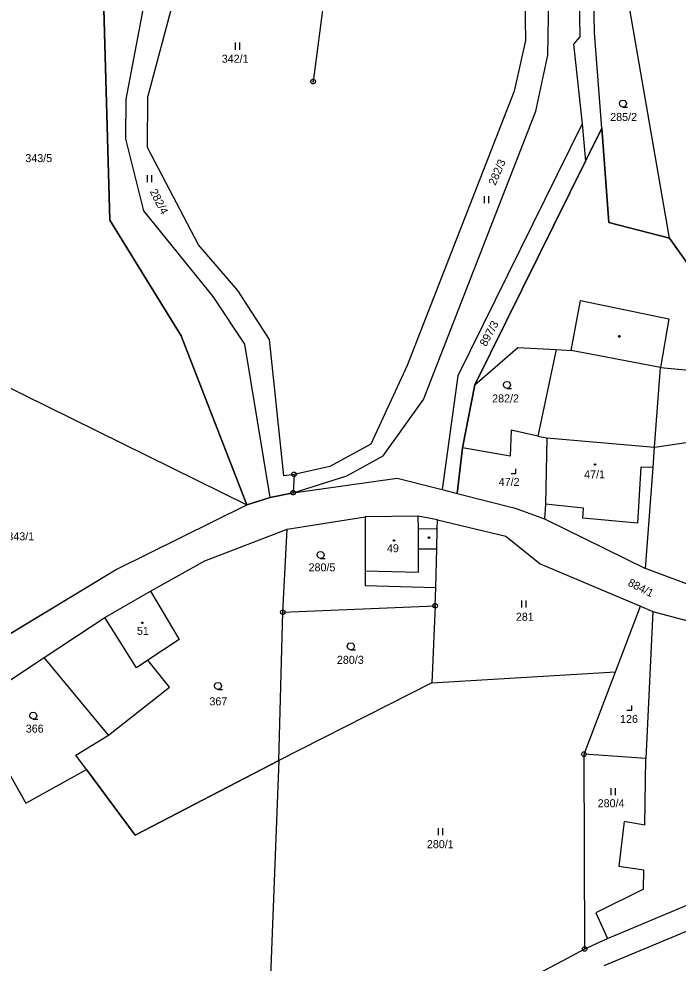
# Model space of a CAD drawing. Extents: x -580551 to -575069, y -1073031 to -1067931.
# Drawn here: x -577343.9 to -577203.9, y -1069968.7 to -1069768.1 of the extents above; entities that cross this region are included whole.
import ezdxf

# ---------------------------------------------------------------- set-up
doc = ezdxf.new("R2010")
doc.units = 0
for name, color, linetype in [('Druh pozemku', 7, 'Continuous'), ('Geodetické body', 7, 'Continuous'), ('Hranice z DKM', 7, 'Continuous'), ('Parcela', 7, 'Continuous'), ('Parcelní číslo', 7, 'Continuous'), ('Parcelní číslo_stavba', 7, 'Continuous'), ('SR - hranice státu', 7, 'Continuous'), ('Vnitřní kresba', 7, 'Continuous'), ('Vrstva 6', 7, 'Continuous')]:
    doc.layers.add(name, color=color, linetype=linetype)

msp = doc.modelspace()

# ---------------------------------------------------------------- linework, layer by layer
at = {"layer": 'Druh pozemku'}
for p, q in [((-577297.96, -1069773.18), (-577297.96, -1069774.68)), ((-577296.96, -1069774.68), (-577296.96, -1069773.18)), ((-577316.64, -1069801.35), (-577316.64, -1069802.85)), ((-577315.64, -1069802.85), (-577315.64, -1069801.35)), ((-577245.06, -1069805.78), (-577245.06, -1069807.28)), ((-577244.06, -1069807.28), (-577244.06, -1069805.78)), ((-577237.12, -1069891.66), (-577237.12, -1069893.16)), ((-577236.12, -1069893.16), (-577236.12, -1069891.66)), ((-577218.17, -1069931.53), (-577218.17, -1069933.03)), ((-577217.17, -1069933.03), (-577217.17, -1069931.53)), ((-577254.83, -1069940.05), (-577254.83, -1069941.55)), ((-577253.83, -1069941.55), (-577253.83, -1069940.05))]:
    msp.add_line(p, q, dxfattribs=at)
for points in [[(-577215.58, -1069786.86), (-577215.96, -1069786.76), (-577216.23, -1069786.49), (-577216.33, -1069786.12), (-577216.23, -1069785.75), (-577215.96, -1069785.48), (-577215.59, -1069785.38), (-577215.22, -1069785.48), (-577214.95, -1069785.75), (-577214.85, -1069786.13), (-577214.95, -1069786.51), (-577215.22, -1069786.78), (-577215.6, -1069786.88), (-577214.6, -1069786.88)], [(-577240.21, -1069846.62), (-577240.59, -1069846.52), (-577240.86, -1069846.25), (-577240.96, -1069845.88), (-577240.86, -1069845.51), (-577240.59, -1069845.24), (-577240.22, -1069845.14), (-577239.85, -1069845.24), (-577239.58, -1069845.51), (-577239.48, -1069845.89), (-577239.58, -1069846.27), (-577239.85, -1069846.54), (-577240.23, -1069846.64), (-577239.23, -1069846.64)], [(-577239.34, -1069864.71), (-577238.34, -1069864.71), (-577238.34, -1069863.71)], [(-577279.8, -1069882.74), (-577280.18, -1069882.64), (-577280.45, -1069882.37), (-577280.55, -1069882), (-577280.45, -1069881.63), (-577280.18, -1069881.36), (-577279.81, -1069881.26), (-577279.44, -1069881.36), (-577279.17, -1069881.63), (-577279.07, -1069882.01), (-577279.17, -1069882.39), (-577279.44, -1069882.66), (-577279.82, -1069882.76), (-577278.82, -1069882.76)], [(-577273.39, -1069902.15), (-577273.77, -1069902.05), (-577274.04, -1069901.78), (-577274.14, -1069901.41), (-577274.04, -1069901.04), (-577273.77, -1069900.77), (-577273.4, -1069900.67), (-577273.03, -1069900.77), (-577272.76, -1069901.04), (-577272.66, -1069901.42), (-577272.76, -1069901.8), (-577273.03, -1069902.07), (-577273.41, -1069902.17), (-577272.41, -1069902.17)], [(-577301.58, -1069910.56), (-577301.96, -1069910.46), (-577302.23, -1069910.19), (-577302.33, -1069909.82), (-577302.23, -1069909.45), (-577301.96, -1069909.18), (-577301.59, -1069909.08), (-577301.22, -1069909.18), (-577300.95, -1069909.45), (-577300.85, -1069909.83), (-577300.95, -1069910.21), (-577301.22, -1069910.48), (-577301.6, -1069910.58), (-577300.6, -1069910.58)], [(-577340.82, -1069916.88), (-577341.2, -1069916.78), (-577341.47, -1069916.51), (-577341.57, -1069916.14), (-577341.47, -1069915.77), (-577341.2, -1069915.5), (-577340.83, -1069915.4), (-577340.46, -1069915.5), (-577340.19, -1069915.77), (-577340.09, -1069916.15), (-577340.19, -1069916.53), (-577340.46, -1069916.8), (-577340.84, -1069916.9), (-577339.84, -1069916.9)], [(-577214.73, -1069914.99), (-577213.73, -1069914.99), (-577213.73, -1069913.99)]]:
    msp.add_lwpolyline(points, dxfattribs=at)
for points in [[(-577216.26, -1069835.42), (-577216.17, -1069835.57), (-577216.26, -1069835.72), (-577216.44, -1069835.72), (-577216.53, -1069835.57), (-577216.44, -1069835.42)], [(-577221.45, -1069862.62), (-577221.36, -1069862.77), (-577221.45, -1069862.92), (-577221.63, -1069862.92), (-577221.72, -1069862.77), (-577221.63, -1069862.62)], [(-577264.11, -1069878.8), (-577264.02, -1069878.95), (-577264.11, -1069879.1), (-577264.29, -1069879.1), (-577264.38, -1069878.95), (-577264.29, -1069878.8)], [(-577256.67, -1069878.19), (-577256.58, -1069878.34), (-577256.67, -1069878.49), (-577256.85, -1069878.49), (-577256.94, -1069878.34), (-577256.85, -1069878.19)], [(-577317.56, -1069896.28), (-577317.47, -1069896.43), (-577317.56, -1069896.58), (-577317.74, -1069896.58), (-577317.83, -1069896.43), (-577317.74, -1069896.28)]]:
    msp.add_lwpolyline(points, close=True, dxfattribs=at)
at = {"layer": 'Geodetické body'}
for p, q in [((-577281.5, -1069781.45), (-577281.26, -1069781.45)), ((-577285.55, -1069864.9), (-577285.31, -1069864.9)), ((-577285.74, -1069868.8), (-577285.5, -1069868.8)), ((-577255.59, -1069892.81), (-577255.35, -1069892.81)), ((-577287.92, -1069894.19), (-577287.68, -1069894.19)), ((-577223.97, -1069924.33), (-577223.73, -1069924.33)), ((-577223.83, -1069965.71), (-577223.59, -1069965.71))]:
    msp.add_line(p, q, dxfattribs=at)
for points in [[(-577281.23, -1069780.97), (-577280.98, -1069781.15), (-577280.88, -1069781.44), (-577280.98, -1069781.73), (-577281.23, -1069781.91), (-577281.54, -1069781.91), (-577281.79, -1069781.73), (-577281.89, -1069781.44), (-577281.79, -1069781.15), (-577281.54, -1069780.97)], [(-577285.28, -1069864.42), (-577285.03, -1069864.6), (-577284.93, -1069864.89), (-577285.03, -1069865.18), (-577285.28, -1069865.36), (-577285.59, -1069865.36), (-577285.84, -1069865.18), (-577285.94, -1069864.89), (-577285.84, -1069864.6), (-577285.59, -1069864.42)], [(-577285.47, -1069868.32), (-577285.22, -1069868.5), (-577285.12, -1069868.79), (-577285.22, -1069869.08), (-577285.47, -1069869.26), (-577285.78, -1069869.26), (-577286.03, -1069869.08), (-577286.13, -1069868.79), (-577286.03, -1069868.5), (-577285.78, -1069868.32)], [(-577287.65, -1069893.71), (-577287.4, -1069893.89), (-577287.3, -1069894.18), (-577287.4, -1069894.47), (-577287.65, -1069894.65), (-577287.96, -1069894.65), (-577288.21, -1069894.47), (-577288.31, -1069894.18), (-577288.21, -1069893.89), (-577287.96, -1069893.71)], [(-577255.32, -1069892.33), (-577255.07, -1069892.51), (-577254.97, -1069892.8), (-577255.07, -1069893.09), (-577255.32, -1069893.27), (-577255.63, -1069893.27), (-577255.88, -1069893.09), (-577255.98, -1069892.8), (-577255.88, -1069892.51), (-577255.63, -1069892.33)], [(-577223.7, -1069923.85), (-577223.45, -1069924.03), (-577223.35, -1069924.32), (-577223.45, -1069924.61), (-577223.7, -1069924.79), (-577224.01, -1069924.79), (-577224.26, -1069924.61), (-577224.36, -1069924.32), (-577224.26, -1069924.03), (-577224.01, -1069923.85)], [(-577223.56, -1069965.23), (-577223.31, -1069965.41), (-577223.21, -1069965.7), (-577223.31, -1069965.99), (-577223.56, -1069966.17), (-577223.87, -1069966.17), (-577224.12, -1069965.99), (-577224.22, -1069965.7), (-577224.12, -1069965.41), (-577223.87, -1069965.23)]]:
    msp.add_lwpolyline(points, close=True, dxfattribs=at)
at = {"layer": 'Hranice z DKM'}
msp.add_lwpolyline([(-577324.89, -1069726.66), (-577326.18, -1069753.47), (-577324.56, -1069810.92), (-577309.38, -1069835.47), (-577295.46, -1069871.36)], dxfattribs=at)
at = {"layer": 'Parcela'}
for p, q in [((-577225.74, -1069711.96), (-577224.72, -1069771.95)), ((-577205.71, -1069814.7), (-577223.18, -1069713.24)), ((-577221.6, -1069771.08), (-577223.18, -1069713.24)), ((-577300.14, -1069723.1), (-577316.47, -1069784.57)), ((-577231.53, -1069775.83), (-577230.82, -1069724.31)), ((-577236.87, -1069727.44), (-577236.28, -1069772.73)), ((-577276.54, -1069744.84), (-577281.38, -1069781.45)), ((-577324.56, -1069810.92), (-577326.18, -1069753.47)), ((-577321.11, -1069785.16), (-577315.7, -1069757.11)), ((-577220.08, -1069791.36), (-577221.6, -1069771.08)), ((-577236.28, -1069772.73), (-577238.72, -1069783.5)), ((-577224.72, -1069771.95), (-577226.09, -1069773.52)), ((-577226.09, -1069773.52), (-577224.26, -1069790.42)), ((-577234.1, -1069787.75), (-577231.53, -1069775.83)), ((-577238.72, -1069783.5), (-577261.41, -1069841.79)), ((-577321.13, -1069793.6), (-577321.11, -1069785.16)), ((-577316.53, -1069795.46), (-577316.47, -1069784.57)), ((-577257.96, -1069848.97), (-577234.1, -1069787.75)), ((-577224.26, -1069790.42), (-577250.62, -1069843.96)), ((-577220.08, -1069791.36), (-577223.56, -1069798.39)), ((-577218.58, -1069811.4), (-577220.08, -1069791.36)), ((-577317.34, -1069808.9), (-577321.13, -1069793.6)), ((-577305.72, -1069816.14), (-577316.53, -1069795.46)), ((-577223.56, -1069798.39), (-577247.03, -1069845.89)), ((-577302.59, -1069827.11), (-577317.34, -1069808.9)), ((-577309.38, -1069835.47), (-577324.56, -1069810.92)), ((-577205.71, -1069814.7), (-577218.58, -1069811.4)), ((-577185.48, -1069843.33), (-577205.71, -1069814.7)), ((-577297.37, -1069825.86), (-577305.72, -1069816.14)), ((-577295.86, -1069837.2), (-577302.59, -1069827.11)), ((-577290.64, -1069836.25), (-577297.37, -1069825.86)), ((-577295.46, -1069871.36), (-577309.38, -1069835.47)), ((-577290.48, -1069869.82), (-577295.86, -1069837.2)), ((-577287.63, -1069865.19), (-577290.64, -1069836.25)), ((-577247.03, -1069845.89), (-577237.93, -1069837.93)), ((-577237.93, -1069837.93), (-577229.77, -1069838.35)), ((-577229.77, -1069838.35), (-577233.66, -1069856.79)), ((-577353.77, -1069842.63), (-577295.46, -1069871.36)), ((-577261.41, -1069841.79), (-577269.12, -1069858.46)), ((-577208.88, -1069859.13), (-577207.6, -1069842.17)), ((-577207.6, -1069842.17), (-577188.34, -1069843.99)), ((-577250.62, -1069843.96), (-577253.98, -1069868.14)), ((-577247.03, -1069845.89), (-577249.65, -1069859.24)), ((-577266.5, -1069860.95), (-577257.96, -1069848.97)), ((-577239.34, -1069855.53), (-577239.55, -1069861.06)), ((-577233.66, -1069856.79), (-577239.34, -1069855.53)), ((-577233.66, -1069856.79), (-577231.72, -1069857.16)), ((-577231.72, -1069857.16), (-577232.07, -1069871.21)), ((-577208.88, -1069859.13), (-577191.14, -1069856.54)), ((-577269.12, -1069858.46), (-577277.83, -1069863.22)), ((-577249.65, -1069859.24), (-577250.76, -1069868.95)), ((-577239.55, -1069861.06), (-577249.65, -1069859.24)), ((-577209.2, -1069863.44), (-577208.88, -1069859.13)), ((-577274.25, -1069865.2), (-577266.5, -1069860.95)), ((-577277.83, -1069863.22), (-577285.43, -1069864.9)), ((-577210.81, -1069884.91), (-577209.2, -1069863.44)), ((-577285.43, -1069864.9), (-577287.63, -1069865.19)), ((-577285.43, -1069864.9), (-577285.62, -1069868.8)), ((-577285.62, -1069868.8), (-577274.25, -1069865.2)), ((-577285.62, -1069868.8), (-577263.51, -1069865.73)), ((-577263.51, -1069865.73), (-577253.98, -1069868.14)), ((-577290.48, -1069869.82), (-577295.46, -1069871.36)), ((-577285.62, -1069868.8), (-577290.48, -1069869.82)), ((-577253.98, -1069868.14), (-577250.76, -1069868.95)), ((-577250.76, -1069868.95), (-577238.45, -1069872.07)), ((-577323.38, -1069885.15), (-577295.46, -1069871.36)), ((-577232.07, -1069871.21), (-577232.25, -1069874.31)), ((-577259.07, -1069873.76), (-577270.35, -1069873.92)), ((-577254.98, -1069874.53), (-577259.07, -1069873.76)), ((-577238.45, -1069872.07), (-577232.25, -1069874.31)), ((-577286.87, -1069876.53), (-577270.35, -1069873.92)), ((-577270.35, -1069873.92), (-577270.34, -1069885.39)), ((-577255.06, -1069876.54), (-577254.98, -1069874.53)), ((-577254.98, -1069874.53), (-577240.49, -1069878.01)), ((-577232.25, -1069874.31), (-577210.81, -1069884.91)), ((-577304.4, -1069883.25), (-577286.87, -1069876.53)), ((-577287.8, -1069894.19), (-577286.87, -1069876.53)), ((-577255.14, -1069880.74), (-577255.06, -1069876.54)), ((-577240.49, -1069878.01), (-577233.14, -1069883.91)), ((-577255.3, -1069888.94), (-577255.14, -1069880.74)), ((-577315.89, -1069889.69), (-577304.4, -1069883.25)), ((-577364.42, -1069909.96), (-577323.38, -1069885.15)), ((-577270.34, -1069885.39), (-577270.34, -1069888.48)), ((-577233.14, -1069883.91), (-577211.86, -1069892.91)), ((-577195.72, -1069890.5), (-577210.81, -1069884.91)), ((-577325.63, -1069895.3), (-577315.89, -1069889.69)), ((-577315.89, -1069889.69), (-577309.81, -1069899.98)), ((-577270.34, -1069888.48), (-577255.3, -1069888.94)), ((-577255.47, -1069892.81), (-577255.3, -1069888.94)), ((-577287.8, -1069894.19), (-577255.47, -1069892.81)), ((-577255.47, -1069892.81), (-577256.18, -1069909.15)), ((-577217.17, -1069906.82), (-577211.86, -1069892.91)), ((-577211.86, -1069892.91), (-577209.21, -1069894.03)), ((-577338.5, -1069903.82), (-577325.63, -1069895.3)), ((-577288.66, -1069925.7), (-577287.8, -1069894.19)), ((-577209.21, -1069894.03), (-577210.7, -1069925.24)), ((-577209.21, -1069894.03), (-577201.02, -1069896.19)), ((-577309.81, -1069899.98), (-577316.47, -1069904.38)), ((-577354.01, -1069914.08), (-577338.5, -1069903.82)), ((-577324.82, -1069920.26), (-577338.5, -1069903.82)), ((-577311.9, -1069910.08), (-577316.47, -1069904.38)), ((-577256.18, -1069909.15), (-577217.17, -1069906.82)), ((-577223.85, -1069924.33), (-577217.17, -1069906.82)), ((-577256.18, -1069909.15), (-577288.66, -1069925.7)), ((-577324.82, -1069920.26), (-577311.9, -1069910.08)), ((-577331.76, -1069924.55), (-577324.82, -1069920.26)), ((-577329.51, -1069927.59), (-577331.76, -1069924.55)), ((-577288.66, -1069925.7), (-577319.14, -1069941.51)), ((-577288.66, -1069925.7), (-577291.47, -1069999.12)), ((-577223.71, -1069965.71), (-577223.85, -1069924.33)), ((-577210.7, -1069925.24), (-577223.85, -1069924.33)), ((-577210.96, -1069939.41), (-577210.7, -1069925.24)), ((-577342.36, -1069934.74), (-577329.51, -1069927.59)), ((-577319.14, -1069941.51), (-577329.51, -1069927.59)), ((-577344.57, -1069930.83), (-577342.36, -1069934.74)), ((-577215.31, -1069938.61), (-577216.49, -1069948.13)), ((-577210.96, -1069939.41), (-577215.31, -1069938.61)), ((-577216.49, -1069948.13), (-577211.13, -1069948.92)), ((-577211.21, -1069952.99), (-577211.13, -1069948.92)), ((-577211.21, -1069952.99), (-577221.32, -1069958.05)), ((-577221.32, -1069958.05), (-577218.87, -1069963.52)), ((-577218.87, -1069963.52), (-577201.68, -1069956.25)), ((-577197.02, -1069959.85), (-577219.63, -1069969.3)), ((-577223.71, -1069965.71), (-577218.87, -1069963.52)), ((-577227.38, -1069967.65), (-577223.71, -1069965.71)), ((-577255.36, -1069982.47), (-577227.38, -1069967.65))]:
    msp.add_line(p, q, dxfattribs=at)
at = {"layer": 'SR - hranice státu'}
for p, q in [((-577223.56, -1069798.39), (-577220.08, -1069791.36)), ((-577288.66, -1069925.7), (-577291.47, -1069999.12))]:
    msp.add_line(p, q, dxfattribs=at)
for points in [[(-577220.08, -1069791.36), (-577218.58, -1069811.4), (-577205.71, -1069814.7), (-577185.48, -1069843.33)], [(-577250.76, -1069868.95), (-577249.65, -1069859.24), (-577247.03, -1069845.89), (-577223.56, -1069798.39)], [(-577285.62, -1069868.8), (-577263.51, -1069865.73), (-577253.98, -1069868.14), (-577250.76, -1069868.95)], [(-577386.06, -1069921.75), (-577364.42, -1069909.96), (-577323.38, -1069885.15), (-577295.46, -1069871.36), (-577290.48, -1069869.82), (-577285.62, -1069868.8)], [(-577354.01, -1069914.08), (-577344.57, -1069930.83), (-577342.36, -1069934.74), (-577329.51, -1069927.59)], [(-577223.71, -1069965.71), (-577218.87, -1069963.52), (-577201.68, -1069956.25), (-577189.32, -1069952.46), (-577173.9, -1069944.95), (-577156.97, -1069935), (-577127.87, -1069920.6), (-577123.8, -1069922.68)], [(-577329.51, -1069927.59), (-577319.14, -1069941.51), (-577288.66, -1069925.7)], [(-577291.47, -1069999.12), (-577284.41, -1069995.28), (-577255.36, -1069982.47), (-577227.38, -1069967.65), (-577223.71, -1069965.71)]]:
    msp.add_lwpolyline(points, dxfattribs=at)
at = {"layer": 'Vnitřní kresba'}
for p, q in [((-577226.57, -1069838.55), (-577224.59, -1069827.97)), ((-577224.59, -1069827.97), (-577205.86, -1069831.84)), ((-577205.86, -1069831.84), (-577207.6, -1069842.17)), ((-577229.77, -1069838.35), (-577226.57, -1069838.55)), ((-577207.6, -1069842.17), (-577226.57, -1069838.55)), ((-577231.72, -1069857.16), (-577208.88, -1069859.13)), ((-577211.78, -1069863.37), (-577212.53, -1069875.29)), ((-577209.2, -1069863.44), (-577211.78, -1069863.37)), ((-577223.95, -1069872.05), (-577232.07, -1069871.21)), ((-577259.04, -1069876.48), (-577259.07, -1069873.76)), ((-577224.12, -1069874.16), (-577223.95, -1069872.05)), ((-577212.53, -1069875.29), (-577224.12, -1069874.16)), ((-577255.06, -1069876.54), (-577259.04, -1069876.48)), ((-577259.03, -1069880.71), (-577259.04, -1069876.48)), ((-577259.01, -1069885.68), (-577259.03, -1069880.71)), ((-577259.03, -1069880.71), (-577255.14, -1069880.74)), ((-577270.34, -1069885.39), (-577259.01, -1069885.68)), ((-577318.91, -1069905.99), (-577325.63, -1069895.3)), ((-577316.47, -1069904.38), (-577318.91, -1069905.99))]:
    msp.add_line(p, q, dxfattribs=at)
at = {"layer": 'Vrstva 6'}
msp.add_line((-577224.26, -1069790.42), (-577223.56, -1069798.39), dxfattribs=at)

# ---------------------------------------------------------------- texts
at = {"layer": 'Parcelní číslo'}
for s, p in [('342/1', (-577300.784, -1069777.45)), ('285/2', (-577218.294, -1069789.82)), ('343/5', (-577342.494, -1069798.56)), ('282/2', (-577243.358, -1069849.61)), ('343/1', (-577346.316, -1069878.91)), ('280/5', (-577282.343, -1069885.49)), ('281', (-577238.326, -1069895.99)), ('280/3', (-577276.328, -1069905.14)), ('367', (-577303.406, -1069913.95)), ('366', (-577342.401, -1069919.75)), ('280/4', (-577220.951, -1069935.6)), ('280/1', (-577257.224, -1069944.3))]:
    msp.add_text(s, height=1.7, dxfattribs=at).set_placement(p)
for s, rotation, p in [('282/3', 66.69229, (-577242.68, -1069803.644)), ('282/4', 296.90673, (-577316.13, -1069804.782)), ('897/3', 61.36378, (-577244.643, -1069837.856)), ('884/1', 332.88848, (-577214.685, -1069888.438))]:
    msp.add_text(s, height=1.7, rotation=rotation, dxfattribs=at).set_placement(p)
at = {"layer": 'Parcelní číslo_stavba'}
for s, p in [('47/2', (-577241.971, -1069867.35)), ('47/1', (-577223.829, -1069865.73)), ('49', (-577265.706, -1069881.43)), ('51', (-577318.81, -1069898.98)), ('126', (-577216.202, -1069917.69))]:
    msp.add_text(s, height=1.7, dxfattribs=at).set_placement(p)

doc.saveas('drawing.dxf')
